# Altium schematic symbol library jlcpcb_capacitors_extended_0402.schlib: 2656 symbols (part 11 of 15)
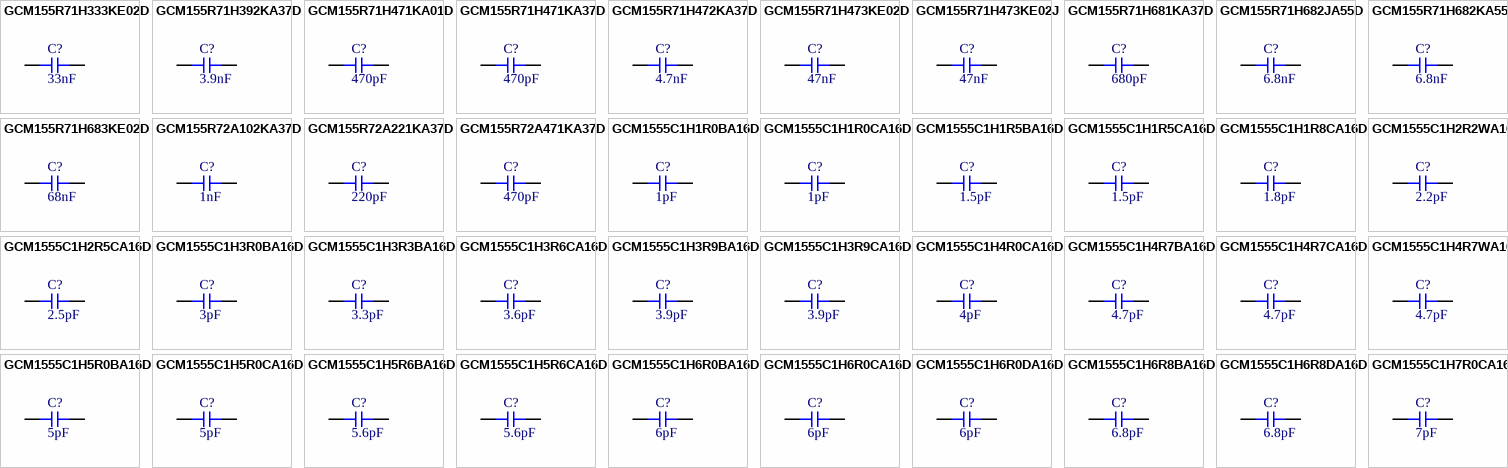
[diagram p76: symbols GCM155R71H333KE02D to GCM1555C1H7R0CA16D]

## GCM1555C1H4R7BA16D
designator C?  Capacitance: 4.7pF  (hidden comment: *)
Capacitor, Ceramic (MLCC), 4.7pF, ±0.1pF, 50V, C0G, ±0.1pF, SMD 0402; Manufacturer: Murata Electronics; Manufacturer Part Number: GCM1555C1H4R7BA16D
footprint CAP-0402 (0402 (1005M) Capacitor)
pins: 1, 2

## GCM1555C1H4R7CA16D
designator C?  Capacitance: 4.7pF  (hidden comment: *)
Capacitor, Ceramic (MLCC), 4.7pF, ±0.25pF, 50V, C0G, ±0.25pF, SMD 0402; Manufacturer: Murata Electronics; Manufacturer Part Number: GCM1555C1H4R7CA16D
footprint CAP-0402 (0402 (1005M) Capacitor)
pins: 1, 2

## GCM1555C1H4R7WA16D
designator C?  Capacitance: 4.7pF  (hidden comment: *)
Capacitor, Ceramic (MLCC), 4.7pF, ±0.05pF, 50V, C0G, ±0.05pF, SMD 0402; Manufacturer: Murata Electronics; Manufacturer Part Number: GCM1555C1H4R7WA16D
footprint CAP-0402 (0402 (1005M) Capacitor)
pins: 1, 2

## GCM1555C1H5R0BA16D
designator C?  Capacitance: 5pF  (hidden comment: *)
Capacitor, Ceramic (MLCC), 5pF, ±0.1pF, ±0.1pF, SMD 0402; Manufacturer: Murata Electronics; Manufacturer Part Number: GCM1555C1H5R0BA16D
footprint CAP-0402 (0402 (1005M) Capacitor)
pins: 1, 2

## GCM1555C1H5R0CA16D
designator C?  Capacitance: 5pF  (hidden comment: *)
Capacitor, Ceramic (MLCC), 5pF, ±0.25pF, 50V, C0G, ±0.25pF, SMD 0402; Manufacturer: Murata Electronics; Manufacturer Part Number: GCM1555C1H5R0CA16D
footprint CAP-0402 (0402 (1005M) Capacitor)
pins: 1, 2

## GCM1555C1H5R6BA16D
designator C?  Capacitance: 5.6pF  (hidden comment: *)
Capacitor, Ceramic (MLCC), 5.6pF, ±0.1pF, 50V, C0G, ±0.1pF, SMD 0402; Manufacturer: Murata Electronics; Manufacturer Part Number: GCM1555C1H5R6BA16D
footprint CAP-0402 (0402 (1005M) Capacitor)
pins: 1, 2

## GCM1555C1H5R6CA16D
designator C?  Capacitance: 5.6pF  (hidden comment: *)
Capacitor, Ceramic (MLCC), 5.6pF, ±0.25pF, 50V, C0G, ±0.25pF, SMD 0402; Manufacturer: Murata Electronics; Manufacturer Part Number: GCM1555C1H5R6CA16D
footprint CAP-0402 (0402 (1005M) Capacitor)
pins: 1, 2

## GCM1555C1H6R0BA16D
designator C?  Capacitance: 6pF  (hidden comment: *)
Capacitor, Ceramic (MLCC), 6pF, ±0.1pF, 50V, C0G, ±0.1pF, SMD 0402; Manufacturer: Murata Electronics; Manufacturer Part Number: GCM1555C1H6R0BA16D
footprint CAP-0402 (0402 (1005M) Capacitor)
pins: 1, 2

## GCM1555C1H6R0CA16D
designator C?  Capacitance: 6pF  (hidden comment: *)
Capacitor, Ceramic (MLCC), 6pF, ±0.25pF, 50V, C0G, ±0.25pF, SMD 0402; Manufacturer: Murata Electronics; Manufacturer Part Number: GCM1555C1H6R0CA16D
footprint CAP-0402 (0402 (1005M) Capacitor)
pins: 1, 2

## GCM1555C1H6R0DA16D
designator C?  Capacitance: 6pF  (hidden comment: *)
Capacitor, Ceramic (MLCC), 6pF, ±0.5pF, 50V, C0G, ±0.5pF, SMD 0402; Manufacturer: Murata Electronics; Manufacturer Part Number: GCM1555C1H6R0DA16D
footprint CAP-0402 (0402 (1005M) Capacitor)
pins: 1, 2

## GCM1555C1H6R8BA16D
designator C?  Capacitance: 6.8pF  (hidden comment: *)
Capacitor, Ceramic (MLCC), 6.8pF, ±0.1pF, 50V, C0G, ±0.1pF, SMD 0402; Manufacturer: Murata Electronics; Manufacturer Part Number: GCM1555C1H6R8BA16D
footprint CAP-0402 (0402 (1005M) Capacitor)
pins: 1, 2

## GCM1555C1H6R8DA16D
designator C?  Capacitance: 6.8pF  (hidden comment: *)
Capacitor, Ceramic (MLCC), 6.8pF, ±0.5pF, 50V, C0G, ±0.5pF, SMD 0402; Manufacturer: Murata Electronics; Manufacturer Part Number: GCM1555C1H6R8DA16D
footprint CAP-0402 (0402 (1005M) Capacitor)
pins: 1, 2

## GCM1555C1H7R0CA16D
designator C?  Capacitance: 7pF  (hidden comment: *)
Capacitor, Ceramic (MLCC), 7pF, ±0.25pF, 50V, C0G, ±0.25pF, SMD 0402; Manufacturer: Murata Electronics; Manufacturer Part Number: GCM1555C1H7R0CA16D
footprint CAP-0402 (0402 (1005M) Capacitor)
pins: 1, 2

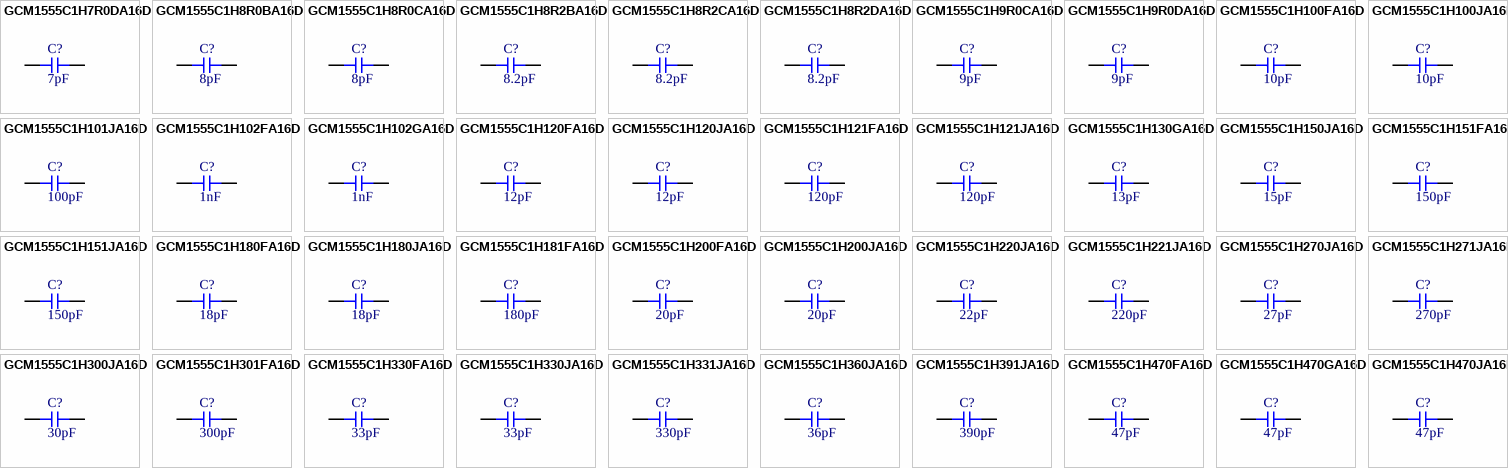
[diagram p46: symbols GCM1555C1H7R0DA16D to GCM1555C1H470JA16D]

## GCM1555C1H7R0DA16D
designator C?  Capacitance: 7pF  (hidden comment: *)
Capacitor, Ceramic (MLCC), 7pF, ±0.5pF, 50V, C0G, ±0.5pF, SMD 0402; Manufacturer: Murata Electronics; Manufacturer Part Number: GCM1555C1H7R0DA16D
footprint CAP-0402 (0402 (1005M) Capacitor)
pins: 1, 2

## GCM1555C1H8R0BA16D
designator C?  Capacitance: 8pF  (hidden comment: *)
Capacitor, Ceramic (MLCC), 8pF, ±0.1pF, 50V, C0G, ±0.1pF, SMD 0402; Manufacturer: Murata Electronics; Manufacturer Part Number: GCM1555C1H8R0BA16D
footprint CAP-0402 (0402 (1005M) Capacitor)
pins: 1, 2

## GCM1555C1H8R0CA16D
designator C?  Capacitance: 8pF  (hidden comment: *)
Capacitor, Ceramic (MLCC), 8pF, ±0.25pF, 50V, C0G, ±0.25pF, SMD 0402; Manufacturer: Murata Electronics; Manufacturer Part Number: GCM1555C1H8R0CA16D
footprint CAP-0402 (0402 (1005M) Capacitor)
pins: 1, 2

## GCM1555C1H8R2BA16D
designator C?  Capacitance: 8.2pF  (hidden comment: *)
Capacitor, Ceramic (MLCC), 8.2pF, ±0.1pF, 50V, C0G, ±0.1pF, SMD 0402; Manufacturer: Murata Electronics; Manufacturer Part Number: GCM1555C1H8R2BA16D
footprint CAP-0402 (0402 (1005M) Capacitor)
pins: 1, 2

## GCM1555C1H8R2CA16D
designator C?  Capacitance: 8.2pF  (hidden comment: *)
Capacitor, Ceramic (MLCC), 8.2pF, ±0.25pF, 50V, C0G, ±0.25pF, SMD 0402; Manufacturer: Murata Electronics; Manufacturer Part Number: GCM1555C1H8R2CA16D
footprint CAP-0402 (0402 (1005M) Capacitor)
pins: 1, 2

## GCM1555C1H8R2DA16D
designator C?  Capacitance: 8.2pF  (hidden comment: *)
Capacitor, Ceramic (MLCC), 8.2pF, ±0.5pF, 50V, C0G, ±0.5pF, SMD 0402; Manufacturer: Murata Electronics; Manufacturer Part Number: GCM1555C1H8R2DA16D
footprint CAP-0402 (0402 (1005M) Capacitor)
pins: 1, 2

## GCM1555C1H9R0CA16D
designator C?  Capacitance: 9pF  (hidden comment: *)
Capacitor, Ceramic (MLCC), 9pF, ±0.25pF, 50V, C0G, ±0.25pF, SMD 0402; Manufacturer: Murata Electronics; Manufacturer Part Number: GCM1555C1H9R0CA16D
footprint CAP-0402 (0402 (1005M) Capacitor)
pins: 1, 2

## GCM1555C1H9R0DA16D
designator C?  Capacitance: 9pF  (hidden comment: *)
Capacitor, Ceramic (MLCC), 9pF, ±0.5pF, 50V, C0G, ±0.5pF, SMD 0402; Manufacturer: Murata Electronics; Manufacturer Part Number: GCM1555C1H9R0DA16D
footprint CAP-0402 (0402 (1005M) Capacitor)
pins: 1, 2

## GCM1555C1H100FA16D
designator C?  Capacitance: 10pF  (hidden comment: *)
Capacitor, Ceramic (MLCC), 10pF, ±1%, 50V, C0G, ±1%, SMD 0402; Manufacturer: Murata Electronics; Manufacturer Part Number: GCM1555C1H100FA16D
footprint CAP-0402 (0402 (1005M) Capacitor)
pins: 1, 2

## GCM1555C1H100JA16D
designator C?  Capacitance: 10pF  (hidden comment: *)
Capacitor, Ceramic (MLCC), 10pF, ±5%, 50V, C0G, ±5%, SMD 0402; Manufacturer: Murata Electronics; Manufacturer Part Number: GCM1555C1H100JA16D
footprint CAP-0402 (0402 (1005M) Capacitor)
pins: 1, 2

## GCM1555C1H101JA16D
designator C?  Capacitance: 100pF  (hidden comment: *)
Capacitor, Ceramic (MLCC), 100pF, ±5%, 50V, C0G, ±5%, SMD 0402; Manufacturer: Murata Electronics; Manufacturer Part Number: GCM1555C1H101JA16D
footprint CAP-0402 (0402 (1005M) Capacitor)
pins: 1, 2

## GCM1555C1H102FA16D
designator C?  Capacitance: 1nF  (hidden comment: *)
Capacitor, Ceramic (MLCC), 1nF, ±1%, 50V, C0G, ±1%, SMD 0402; Manufacturer: Murata Electronics; Manufacturer Part Number: GCM1555C1H102FA16D
footprint CAP-0402 (0402 (1005M) Capacitor)
pins: 1, 2

## GCM1555C1H102GA16D
designator C?  Capacitance: 1nF  (hidden comment: *)
Capacitor, Ceramic (MLCC), 1nF, ±2%, 50V, C0G, ±2%, SMD 0402; Manufacturer: Murata Electronics; Manufacturer Part Number: GCM1555C1H102GA16D
footprint CAP-0402 (0402 (1005M) Capacitor)
pins: 1, 2

## GCM1555C1H120FA16D
designator C?  Capacitance: 12pF  (hidden comment: *)
Capacitor, Ceramic (MLCC), 12pF, ±1%, 50V, C0G, ±1%, SMD 0402; Manufacturer: Murata Electronics; Manufacturer Part Number: GCM1555C1H120FA16D
footprint CAP-0402 (0402 (1005M) Capacitor)
pins: 1, 2

## GCM1555C1H120JA16D
designator C?  Capacitance: 12pF  (hidden comment: *)
Capacitor, Ceramic (MLCC), 12pF, ±5%, 50V, C0G, ±5%, SMD 0402; Manufacturer: Murata Electronics; Manufacturer Part Number: GCM1555C1H120JA16D
footprint CAP-0402 (0402 (1005M) Capacitor)
pins: 1, 2

## GCM1555C1H121FA16D
designator C?  Capacitance: 120pF  (hidden comment: *)
Capacitor, Ceramic (MLCC), 120pF, ±1%, 50V, C0G, ±1%, SMD 0402; Manufacturer: Murata Electronics; Manufacturer Part Number: GCM1555C1H121FA16D
footprint CAP-0402 (0402 (1005M) Capacitor)
pins: 1, 2

## GCM1555C1H121JA16D
designator C?  Capacitance: 120pF  (hidden comment: *)
Capacitor, Ceramic (MLCC), 120pF, ±5%, 50V, C0G, ±5%, SMD 0402; Manufacturer: Murata Electronics; Manufacturer Part Number: GCM1555C1H121JA16D
footprint CAP-0402 (0402 (1005M) Capacitor)
pins: 1, 2

## GCM1555C1H130GA16D
designator C?  Capacitance: 13pF  (hidden comment: *)
Capacitor, Ceramic (MLCC), 13pF, ±2%, 50V, C0G, ±2%, SMD 0402; Manufacturer: Murata Electronics; Manufacturer Part Number: GCM1555C1H130GA16D
footprint CAP-0402 (0402 (1005M) Capacitor)
pins: 1, 2

## GCM1555C1H150JA16D
designator C?  Capacitance: 15pF  (hidden comment: *)
Capacitor, Ceramic (MLCC), 15pF, ±5%, 50V, C0G, ±5%, SMD 0402; Manufacturer: Murata Electronics; Manufacturer Part Number: GCM1555C1H150JA16D
footprint CAP-0402 (0402 (1005M) Capacitor)
pins: 1, 2

## GCM1555C1H151FA16D
designator C?  Capacitance: 150pF  (hidden comment: *)
Capacitor, Ceramic (MLCC), 150pF, ±1%, 50V, ±1%, SMD 0402; Manufacturer: Murata Electronics; Manufacturer Part Number: GCM1555C1H151FA16D
footprint CAP-0402 (0402 (1005M) Capacitor)
pins: 1, 2

## GCM1555C1H151JA16D
designator C?  Capacitance: 150pF  (hidden comment: *)
Capacitor, Ceramic (MLCC), 150pF, ±5%, 50V, C0G, ±5%, SMD 0402; Manufacturer: Murata Electronics; Manufacturer Part Number: GCM1555C1H151JA16D
footprint CAP-0402 (0402 (1005M) Capacitor)
pins: 1, 2

## GCM1555C1H180FA16D
designator C?  Capacitance: 18pF  (hidden comment: *)
Capacitor, Ceramic (MLCC), 18pF, ±1%, 50V, C0G, ±1%, SMD 0402; Manufacturer: Murata Electronics; Manufacturer Part Number: GCM1555C1H180FA16D
footprint CAP-0402 (0402 (1005M) Capacitor)
pins: 1, 2

## GCM1555C1H180JA16D
designator C?  Capacitance: 18pF  (hidden comment: *)
Capacitor, Ceramic (MLCC), 18pF, ±5%, 50V, C0G, ±5%, SMD 0402; Manufacturer: Murata Electronics; Manufacturer Part Number: GCM1555C1H180JA16D
footprint CAP-0402 (0402 (1005M) Capacitor)
pins: 1, 2

## GCM1555C1H181FA16D
designator C?  Capacitance: 180pF  (hidden comment: *)
Capacitor, Ceramic (MLCC), 180pF, ±1%, 50V, C0G, ±1%, SMD 0402; Manufacturer: Murata Electronics; Manufacturer Part Number: GCM1555C1H181FA16D
footprint CAP-0402 (0402 (1005M) Capacitor)
pins: 1, 2

## GCM1555C1H200FA16D
designator C?  Capacitance: 20pF  (hidden comment: *)
Capacitor, Ceramic (MLCC), 20pF, ±1%, 50V, C0G, ±1%, SMD 0402; Manufacturer: Murata Electronics; Manufacturer Part Number: GCM1555C1H200FA16D
footprint CAP-0402 (0402 (1005M) Capacitor)
pins: 1, 2

## GCM1555C1H200JA16D
designator C?  Capacitance: 20pF  (hidden comment: *)
Capacitor, Ceramic (MLCC), 20pF, ±5%, ±5%, SMD 0402; Manufacturer: Murata Electronics; Manufacturer Part Number: GCM1555C1H200JA16D
footprint CAP-0402 (0402 (1005M) Capacitor)
pins: 1, 2

## GCM1555C1H220JA16D
designator C?  Capacitance: 22pF  (hidden comment: *)
Capacitor, Ceramic (MLCC), 22pF, ±5%, 50V, C0G, ±5%, SMD 0402; Manufacturer: Murata Electronics; Manufacturer Part Number: GCM1555C1H220JA16D
footprint CAP-0402 (0402 (1005M) Capacitor)
pins: 1, 2

## GCM1555C1H221JA16D
designator C?  Capacitance: 220pF  (hidden comment: *)
Capacitor, Ceramic (MLCC), 220pF, ±5%, 50V, C0G, ±5%, SMD 0402; Manufacturer: Murata Electronics; Manufacturer Part Number: GCM1555C1H221JA16D
footprint CAP-0402 (0402 (1005M) Capacitor)
pins: 1, 2

## GCM1555C1H270JA16D
designator C?  Capacitance: 27pF  (hidden comment: *)
Capacitor, Ceramic (MLCC), 27pF, ±5%, 50V, C0G, ±5%, SMD 0402; Manufacturer: Murata Electronics; Manufacturer Part Number: GCM1555C1H270JA16D
footprint CAP-0402 (0402 (1005M) Capacitor)
pins: 1, 2

## GCM1555C1H271JA16D
designator C?  Capacitance: 270pF  (hidden comment: *)
Capacitor, Ceramic (MLCC), 270pF, ±5%, 50V, C0G, ±5%, SMD 0402; Manufacturer: Murata Electronics; Manufacturer Part Number: GCM1555C1H271JA16D
footprint CAP-0402 (0402 (1005M) Capacitor)
pins: 1, 2

## GCM1555C1H300JA16D
designator C?  Capacitance: 30pF  (hidden comment: *)
Capacitor, Ceramic (MLCC), 30pF, ±5%, 50V, C0G, ±5%, SMD 0402; Manufacturer: Murata Electronics; Manufacturer Part Number: GCM1555C1H300JA16D
footprint CAP-0402 (0402 (1005M) Capacitor)
pins: 1, 2

## GCM1555C1H301FA16D
designator C?  Capacitance: 300pF  (hidden comment: *)
Capacitor, Ceramic (MLCC), 300pF, ±1%, 50V, C0G, ±1%, SMD 0402; Manufacturer: Murata Electronics; Manufacturer Part Number: GCM1555C1H301FA16D
footprint CAP-0402 (0402 (1005M) Capacitor)
pins: 1, 2

## GCM1555C1H330FA16D
designator C?  Capacitance: 33pF  (hidden comment: *)
Capacitor, Ceramic (MLCC), 33pF, ±1%, 50V, C0G, ±1%, SMD 0402; Manufacturer: Murata Electronics; Manufacturer Part Number: GCM1555C1H330FA16D
footprint CAP-0402 (0402 (1005M) Capacitor)
pins: 1, 2

## GCM1555C1H330JA16D
designator C?  Capacitance: 33pF  (hidden comment: *)
Capacitor, Ceramic (MLCC), 33pF, ±5%, 50V, C0G, ±5%, SMD 0402; Manufacturer: Murata Electronics; Manufacturer Part Number: GCM1555C1H330JA16D
footprint CAP-0402 (0402 (1005M) Capacitor)
pins: 1, 2

## GCM1555C1H331JA16D
designator C?  Capacitance: 330pF  (hidden comment: *)
Capacitor, Ceramic (MLCC), 330pF, ±5%, 50V, C0G, ±5%, SMD 0402; Manufacturer: Murata Electronics; Manufacturer Part Number: GCM1555C1H331JA16D
footprint CAP-0402 (0402 (1005M) Capacitor)
pins: 1, 2

## GCM1555C1H360JA16D
designator C?  Capacitance: 36pF  (hidden comment: *)
Capacitor, Ceramic (MLCC), 36pF, ±5%, 50V, C0G, ±5%, SMD 0402; Manufacturer: Murata Electronics; Manufacturer Part Number: GCM1555C1H360JA16D
footprint CAP-0402 (0402 (1005M) Capacitor)
pins: 1, 2

## GCM1555C1H391JA16D
designator C?  Capacitance: 390pF  (hidden comment: *)
Capacitor, Ceramic (MLCC), 390pF, ±5%, 50V, C0G, ±5%, SMD 0402; Manufacturer: Murata Electronics; Manufacturer Part Number: GCM1555C1H391JA16D
footprint CAP-0402 (0402 (1005M) Capacitor)
pins: 1, 2

## GCM1555C1H470FA16D
designator C?  Capacitance: 47pF  (hidden comment: *)
Capacitor, Ceramic (MLCC), 47pF, ±1%, 50V, C0G, ±1%, SMD 0402; Manufacturer: Murata Electronics; Manufacturer Part Number: GCM1555C1H470FA16D
footprint CAP-0402 (0402 (1005M) Capacitor)
pins: 1, 2

## GCM1555C1H470GA16D
designator C?  Capacitance: 47pF  (hidden comment: *)
Capacitor, Ceramic (MLCC), 47pF, ±2%, 50V, C0G, ±2%, SMD 0402; Manufacturer: Murata Electronics; Manufacturer Part Number: GCM1555C1H470GA16D
footprint CAP-0402 (0402 (1005M) Capacitor)
pins: 1, 2

## GCM1555C1H470JA16D
designator C?  Capacitance: 47pF  (hidden comment: *)
Capacitor, Ceramic (MLCC), 47pF, ±5%, 50V, C0G, ±5%, SMD 0402; Manufacturer: Murata Electronics; Manufacturer Part Number: GCM1555C1H470JA16D
footprint CAP-0402 (0402 (1005M) Capacitor)
pins: 1, 2

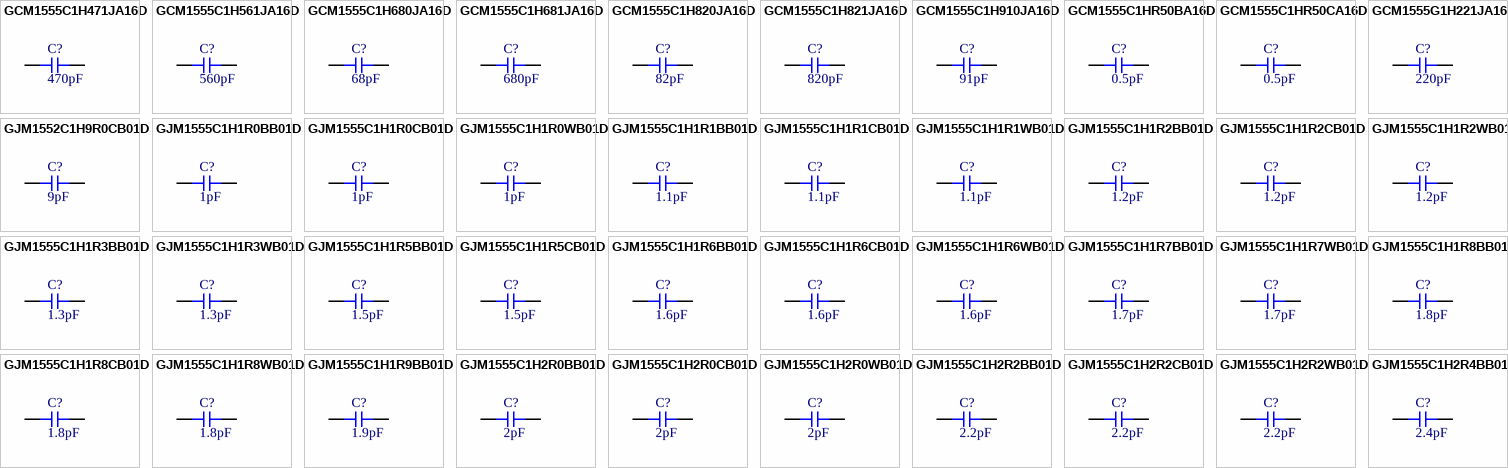
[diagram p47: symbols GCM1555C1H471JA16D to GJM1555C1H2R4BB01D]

## GCM1555C1H471JA16D
designator C?  Capacitance: 470pF  (hidden comment: *)
Capacitor, Ceramic (MLCC), 470pF, ±5%, 50V, C0G, ±5%, SMD 0402; Manufacturer: Murata Electronics; Manufacturer Part Number: GCM1555C1H471JA16D
footprint CAP-0402 (0402 (1005M) Capacitor)
pins: 1, 2

## GCM1555C1H561JA16D
designator C?  Capacitance: 560pF  (hidden comment: *)
Capacitor, Ceramic (MLCC), 560pF, ±5%, 50V, C0G, ±5%, SMD 0402; Manufacturer: Murata Electronics; Manufacturer Part Number: GCM1555C1H561JA16D
footprint CAP-0402 (0402 (1005M) Capacitor)
pins: 1, 2

## GCM1555C1H680JA16D
designator C?  Capacitance: 68pF  (hidden comment: *)
Capacitor, Ceramic (MLCC), 68pF, ±5%, 50V, C0G, ±5%, SMD 0402; Manufacturer: Murata Electronics; Manufacturer Part Number: GCM1555C1H680JA16D
footprint CAP-0402 (0402 (1005M) Capacitor)
pins: 1, 2

## GCM1555C1H681JA16D
designator C?  Capacitance: 680pF  (hidden comment: *)
Capacitor, Ceramic (MLCC), 680pF, ±5%, 50V, C0G, ±5%, SMD 0402; Manufacturer: Murata Electronics; Manufacturer Part Number: GCM1555C1H681JA16D
footprint CAP-0402 (0402 (1005M) Capacitor)
pins: 1, 2

## GCM1555C1H820JA16D
designator C?  Capacitance: 82pF  (hidden comment: *)
Capacitor, Ceramic (MLCC), 82pF, ±5%, 50V, C0G, ±5%, SMD 0402; Manufacturer: Murata Electronics; Manufacturer Part Number: GCM1555C1H820JA16D
footprint CAP-0402 (0402 (1005M) Capacitor)
pins: 1, 2

## GCM1555C1H821JA16D
designator C?  Capacitance: 820pF  (hidden comment: *)
Capacitor, Ceramic (MLCC), 820pF, ±5%, 50V, C0G, ±5%, SMD 0402; Manufacturer: Murata Electronics; Manufacturer Part Number: GCM1555C1H821JA16D
footprint CAP-0402 (0402 (1005M) Capacitor)
pins: 1, 2

## GCM1555C1H910JA16D
designator C?  Capacitance: 91pF  (hidden comment: *)
Capacitor, Ceramic (MLCC), 91pF, ±5%, 50V, ±5%, SMD 0402; Manufacturer: Murata Electronics; Manufacturer Part Number: GCM1555C1H910JA16D
footprint CAP-0402 (0402 (1005M) Capacitor)
pins: 1, 2

## GCM1555C1HR50BA16D
designator C?  Capacitance: 0.5pF  (hidden comment: *)
Capacitor, Ceramic (MLCC), 0.5pF, ±0.1pF, 50V, C0G, ±0.1pF, SMD 0402; Manufacturer: Murata Electronics; Manufacturer Part Number: GCM1555C1HR50BA16D
footprint CAP-0402 (0402 (1005M) Capacitor)
pins: 1, 2

## GCM1555C1HR50CA16D
designator C?  Capacitance: 0.5pF  (hidden comment: *)
Capacitor, Ceramic (MLCC), 0.5pF, ±0.25pF, 50V, C0G, ±0.25pF, SMD 0402; Manufacturer: Murata Electronics; Manufacturer Part Number: GCM1555C1HR50CA16D
footprint CAP-0402 (0402 (1005M) Capacitor)
pins: 1, 2

## GCM1555G1H221JA16D
designator C?  Capacitance: 220pF  (hidden comment: *)
Capacitor, Ceramic (MLCC), 220pF, ±5%, 50V, X6S, ±5%, SMD 0402; Manufacturer: Murata Electronics; Manufacturer Part Number: GCM1555G1H221JA16D
footprint CAP-0402 (0402 (1005M) Capacitor)
pins: 1, 2

## GJM1552C1H9R0CB01D
designator C?  Capacitance: 9pF  (hidden comment: *)
Capacitor, Ceramic (MLCC), 9pF, ±0.25pF, 50V, CH, ±0.25pF, SMD 0402; Manufacturer: Murata Electronics; Manufacturer Part Number: GJM1552C1H9R0CB01D
footprint CAP-0402 (0402 (1005M) Capacitor)
pins: 1, 2

## GJM1555C1H1R0BB01D
designator C?  Capacitance: 1pF  (hidden comment: *)
Capacitor, Ceramic (MLCC), 1pF, ±0.1pF, 50V, C0G, ±0.1pF, SMD 0402; Manufacturer: Murata Electronics; Manufacturer Part Number: GJM1555C1H1R0BB01D
footprint CAP-0402 (0402 (1005M) Capacitor)
pins: 1, 2

## GJM1555C1H1R0CB01D
designator C?  Capacitance: 1pF  (hidden comment: *)
Capacitor, Ceramic (MLCC), 1pF, ±0.25pF, 50V, C0G, ±0.25pF, SMD 0402; Manufacturer: Murata Electronics; Manufacturer Part Number: GJM1555C1H1R0CB01D
footprint CAP-0402 (0402 (1005M) Capacitor)
pins: 1, 2

## GJM1555C1H1R0WB01D
designator C?  Capacitance: 1pF  (hidden comment: *)
Capacitor, Ceramic (MLCC), 1pF, ±0.05pF, 50V, C0G, ±0.05pF, SMD 0402; Manufacturer: Murata Electronics; Manufacturer Part Number: GJM1555C1H1R0WB01D
footprint CAP-0402 (0402 (1005M) Capacitor)
pins: 1, 2

## GJM1555C1H1R1BB01D
designator C?  Capacitance: 1.1pF  (hidden comment: *)
Capacitor, Ceramic (MLCC), 1.1pF, ±0.1pF, 50V, C0G, ±0.1pF, SMD 0402; Manufacturer: Murata Electronics; Manufacturer Part Number: GJM1555C1H1R1BB01D
footprint CAP-0402 (0402 (1005M) Capacitor)
pins: 1, 2

## GJM1555C1H1R1CB01D
designator C?  Capacitance: 1.1pF  (hidden comment: *)
Capacitor, Ceramic (MLCC), 1.1pF, ±0.25pF, 50V, C0G, ±0.25pF, SMD 0402; Manufacturer: Murata Electronics; Manufacturer Part Number: GJM1555C1H1R1CB01D
footprint CAP-0402 (0402 (1005M) Capacitor)
pins: 1, 2

## GJM1555C1H1R1WB01D
designator C?  Capacitance: 1.1pF  (hidden comment: *)
Capacitor, Ceramic (MLCC), 1.1pF, ±0.05pF, 50V, C0G, ±0.05pF, SMD 0402; Manufacturer: Murata Electronics; Manufacturer Part Number: GJM1555C1H1R1WB01D
footprint CAP-0402 (0402 (1005M) Capacitor)
pins: 1, 2

## GJM1555C1H1R2BB01D
designator C?  Capacitance: 1.2pF  (hidden comment: *)
Capacitor, Ceramic (MLCC), 1.2pF, ±0.1pF, 50V, C0G, ±0.1pF, SMD 0402; Manufacturer: Murata Electronics; Manufacturer Part Number: GJM1555C1H1R2BB01D
footprint CAP-0402 (0402 (1005M) Capacitor)
pins: 1, 2

## GJM1555C1H1R2CB01D
designator C?  Capacitance: 1.2pF  (hidden comment: *)
Capacitor, Ceramic (MLCC), 1.2pF, ±0.25pF, 50V, C0G, ±0.25pF, SMD 0402; Manufacturer: Murata Electronics; Manufacturer Part Number: GJM1555C1H1R2CB01D
footprint CAP-0402 (0402 (1005M) Capacitor)
pins: 1, 2

## GJM1555C1H1R2WB01D
designator C?  Capacitance: 1.2pF  (hidden comment: *)
Capacitor, Ceramic (MLCC), 1.2pF, ±0.05pF, 50V, C0G, ±0.05pF, SMD 0402; Manufacturer: Murata Electronics; Manufacturer Part Number: GJM1555C1H1R2WB01D
footprint CAP-0402 (0402 (1005M) Capacitor)
pins: 1, 2

## GJM1555C1H1R3BB01D
designator C?  Capacitance: 1.3pF  (hidden comment: *)
Capacitor, Ceramic (MLCC), 1.3pF, ±0.1pF, 50V, C0G, ±0.1pF, SMD 0402; Manufacturer: Murata Electronics; Manufacturer Part Number: GJM1555C1H1R3BB01D
footprint CAP-0402 (0402 (1005M) Capacitor)
pins: 1, 2

## GJM1555C1H1R3WB01D
designator C?  Capacitance: 1.3pF  (hidden comment: *)
Capacitor, Ceramic (MLCC), 1.3pF, ±0.05pF, 50V, C0G, ±0.05pF, SMD 0402; Manufacturer: Murata Electronics; Manufacturer Part Number: GJM1555C1H1R3WB01D
footprint CAP-0402 (0402 (1005M) Capacitor)
pins: 1, 2

## GJM1555C1H1R5BB01D
designator C?  Capacitance: 1.5pF  (hidden comment: *)
Capacitor, Ceramic (MLCC), 1.5pF, ±0.1pF, 50V, C0G, ±0.1pF, SMD 0402; Manufacturer: Murata Electronics; Manufacturer Part Number: GJM1555C1H1R5BB01D
footprint CAP-0402 (0402 (1005M) Capacitor)
pins: 1, 2

## GJM1555C1H1R5CB01D
designator C?  Capacitance: 1.5pF  (hidden comment: *)
Capacitor, Ceramic (MLCC), 1.5pF, ±0.25pF, 50V, C0G, ±0.25pF, SMD 0402; Manufacturer: Murata Electronics; Manufacturer Part Number: GJM1555C1H1R5CB01D
footprint CAP-0402 (0402 (1005M) Capacitor)
pins: 1, 2

## GJM1555C1H1R6BB01D
designator C?  Capacitance: 1.6pF  (hidden comment: *)
Capacitor, Ceramic (MLCC), 1.6pF, ±0.1pF, 50V, C0G, ±0.1pF, SMD 0402; Manufacturer: Murata Electronics; Manufacturer Part Number: GJM1555C1H1R6BB01D
footprint CAP-0402 (0402 (1005M) Capacitor)
pins: 1, 2

## GJM1555C1H1R6CB01D
designator C?  Capacitance: 1.6pF  (hidden comment: *)
Capacitor, Ceramic (MLCC), 1.6pF, ±0.25pF, 50V, C0G, ±0.25pF, SMD 0402; Manufacturer: Murata Electronics; Manufacturer Part Number: GJM1555C1H1R6CB01D
footprint CAP-0402 (0402 (1005M) Capacitor)
pins: 1, 2

## GJM1555C1H1R6WB01D
designator C?  Capacitance: 1.6pF  (hidden comment: *)
Capacitor, Ceramic (MLCC), 1.6pF, ±0.05pF, 50V, C0G, ±0.05pF, SMD 0402; Manufacturer: Murata Electronics; Manufacturer Part Number: GJM1555C1H1R6WB01D
footprint CAP-0402 (0402 (1005M) Capacitor)
pins: 1, 2

## GJM1555C1H1R7BB01D
designator C?  Capacitance: 1.7pF  (hidden comment: *)
Capacitor, Ceramic (MLCC), 1.7pF, ±0.1pF, 50V, C0G, ±0.1pF, SMD 0402; Manufacturer: Murata Electronics; Manufacturer Part Number: GJM1555C1H1R7BB01D
footprint CAP-0402 (0402 (1005M) Capacitor)
pins: 1, 2

## GJM1555C1H1R7WB01D
designator C?  Capacitance: 1.7pF  (hidden comment: *)
Capacitor, Ceramic (MLCC), 1.7pF, ±0.05pF, 50V, C0G, ±0.05pF, SMD 0402; Manufacturer: Murata Electronics; Manufacturer Part Number: GJM1555C1H1R7WB01D
footprint CAP-0402 (0402 (1005M) Capacitor)
pins: 1, 2

## GJM1555C1H1R8BB01D
designator C?  Capacitance: 1.8pF  (hidden comment: *)
Capacitor, Ceramic (MLCC), 1.8pF, ±0.1pF, 50V, C0G, ±0.1pF, SMD 0402; Manufacturer: Murata Electronics; Manufacturer Part Number: GJM1555C1H1R8BB01D
footprint CAP-0402 (0402 (1005M) Capacitor)
pins: 1, 2

## GJM1555C1H1R8CB01D
designator C?  Capacitance: 1.8pF  (hidden comment: *)
Capacitor, Ceramic (MLCC), 1.8pF, ±0.25pF, 50V, C0G, ±0.25pF, SMD 0402; Manufacturer: Murata Electronics; Manufacturer Part Number: GJM1555C1H1R8CB01D
footprint CAP-0402 (0402 (1005M) Capacitor)
pins: 1, 2

## GJM1555C1H1R8WB01D
designator C?  Capacitance: 1.8pF  (hidden comment: *)
Capacitor, Ceramic (MLCC), 1.8pF, ±0.05pF, 50V, C0G, ±0.05pF, SMD 0402; Manufacturer: Murata Electronics; Manufacturer Part Number: GJM1555C1H1R8WB01D
footprint CAP-0402 (0402 (1005M) Capacitor)
pins: 1, 2

## GJM1555C1H1R9BB01D
designator C?  Capacitance: 1.9pF  (hidden comment: *)
Capacitor, Ceramic (MLCC), 1.9pF, ±0.1pF, 50V, C0G, ±0.1pF, SMD 0402; Manufacturer: Murata Electronics; Manufacturer Part Number: GJM1555C1H1R9BB01D
footprint CAP-0402 (0402 (1005M) Capacitor)
pins: 1, 2

## GJM1555C1H2R0BB01D
designator C?  Capacitance: 2pF  (hidden comment: *)
Capacitor, Ceramic (MLCC), 2pF, ±0.1pF, 50V, C0G, ±0.1pF, SMD 0402; Manufacturer: Murata Electronics; Manufacturer Part Number: GJM1555C1H2R0BB01D
footprint CAP-0402 (0402 (1005M) Capacitor)
pins: 1, 2

## GJM1555C1H2R0CB01D
designator C?  Capacitance: 2pF  (hidden comment: *)
Capacitor, Ceramic (MLCC), 2pF, ±0.25pF, 50V, C0G, ±0.25pF, SMD 0402; Manufacturer: Murata Electronics; Manufacturer Part Number: GJM1555C1H2R0CB01D
footprint CAP-0402 (0402 (1005M) Capacitor)
pins: 1, 2

## GJM1555C1H2R0WB01D
designator C?  Capacitance: 2pF  (hidden comment: *)
Capacitor, Ceramic (MLCC), 2pF, ±0.05pF, 50V, C0G, ±0.05pF, SMD 0402; Manufacturer: Murata Electronics; Manufacturer Part Number: GJM1555C1H2R0WB01D
footprint CAP-0402 (0402 (1005M) Capacitor)
pins: 1, 2

## GJM1555C1H2R2BB01D
designator C?  Capacitance: 2.2pF  (hidden comment: *)
Capacitor, Ceramic (MLCC), 2.2pF, ±0.1pF, 50V, C0G, ±0.1pF, SMD 0402; Manufacturer: Murata Electronics; Manufacturer Part Number: GJM1555C1H2R2BB01D
footprint CAP-0402 (0402 (1005M) Capacitor)
pins: 1, 2

## GJM1555C1H2R2CB01D
designator C?  Capacitance: 2.2pF  (hidden comment: *)
Capacitor, Ceramic (MLCC), 2.2pF, ±0.25pF, 50V, C0G, ±0.25pF, SMD 0402; Manufacturer: Murata Electronics; Manufacturer Part Number: GJM1555C1H2R2CB01D
footprint CAP-0402 (0402 (1005M) Capacitor)
pins: 1, 2

## GJM1555C1H2R2WB01D
designator C?  Capacitance: 2.2pF  (hidden comment: *)
Capacitor, Ceramic (MLCC), 2.2pF, ±0.05pF, 50V, C0G, ±0.05pF, SMD 0402; Manufacturer: Murata Electronics; Manufacturer Part Number: GJM1555C1H2R2WB01D
footprint CAP-0402 (0402 (1005M) Capacitor)
pins: 1, 2

## GJM1555C1H2R4BB01D
designator C?  Capacitance: 2.4pF  (hidden comment: *)
Capacitor, Ceramic (MLCC), 2.4pF, ±0.1pF, 50V, C0G, ±0.1pF, SMD 0402; Manufacturer: Murata Electronics; Manufacturer Part Number: GJM1555C1H2R4BB01D
footprint CAP-0402 (0402 (1005M) Capacitor)
pins: 1, 2

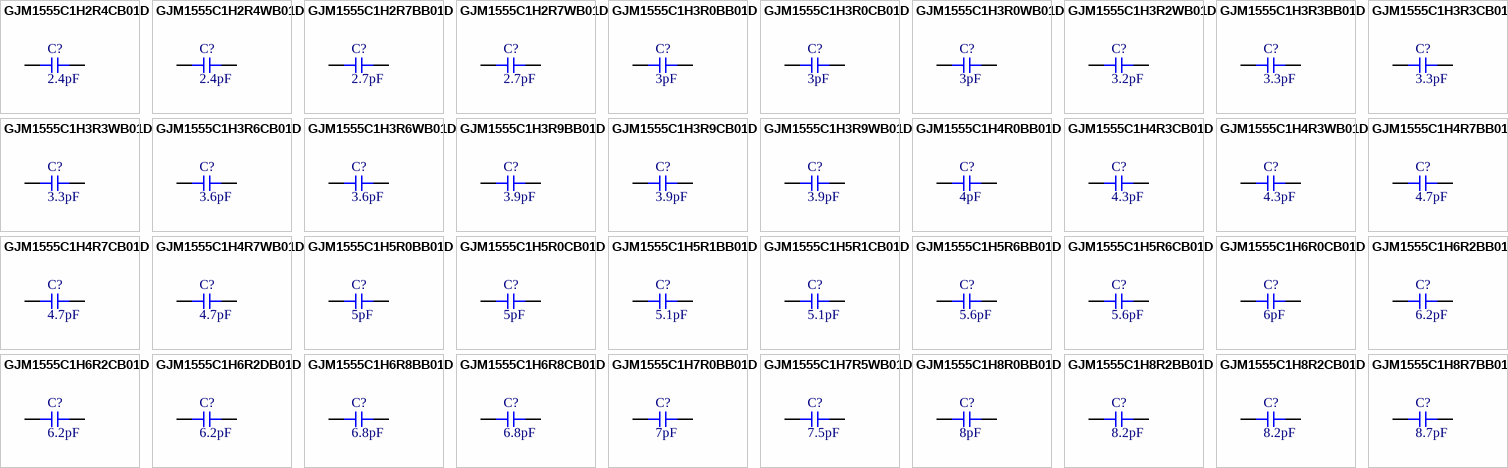
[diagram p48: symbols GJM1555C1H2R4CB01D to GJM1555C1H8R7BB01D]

## GJM1555C1H2R4CB01D
designator C?  Capacitance: 2.4pF  (hidden comment: *)
Capacitor, Ceramic (MLCC), 2.4pF, ±0.25pF, 50V, C0G, ±0.25pF, SMD 0402; Manufacturer: Murata Electronics; Manufacturer Part Number: GJM1555C1H2R4CB01D
footprint CAP-0402 (0402 (1005M) Capacitor)
pins: 1, 2

## GJM1555C1H2R4WB01D
designator C?  Capacitance: 2.4pF  (hidden comment: *)
Capacitor, Ceramic (MLCC), 2.4pF, ±0.05pF, 50V, C0G, ±0.05pF, SMD 0402; Manufacturer: Murata Electronics; Manufacturer Part Number: GJM1555C1H2R4WB01D
footprint CAP-0402 (0402 (1005M) Capacitor)
pins: 1, 2

## GJM1555C1H2R7BB01D
designator C?  Capacitance: 2.7pF  (hidden comment: *)
Capacitor, Ceramic (MLCC), 2.7pF, ±0.1pF, 50V, C0G, ±0.1pF, SMD 0402; Manufacturer: Murata Electronics; Manufacturer Part Number: GJM1555C1H2R7BB01D
footprint CAP-0402 (0402 (1005M) Capacitor)
pins: 1, 2

## GJM1555C1H2R7WB01D
designator C?  Capacitance: 2.7pF  (hidden comment: *)
Capacitor, Ceramic (MLCC), 2.7pF, ±0.05pF, 50V, C0G, ±0.05pF, SMD 0402; Manufacturer: Murata Electronics; Manufacturer Part Number: GJM1555C1H2R7WB01D
footprint CAP-0402 (0402 (1005M) Capacitor)
pins: 1, 2

## GJM1555C1H3R0BB01D
designator C?  Capacitance: 3pF  (hidden comment: *)
Capacitor, Ceramic (MLCC), 3pF, ±0.1pF, 50V, C0G, ±0.1pF, SMD 0402; Manufacturer: Murata Electronics; Manufacturer Part Number: GJM1555C1H3R0BB01D
footprint CAP-0402 (0402 (1005M) Capacitor)
pins: 1, 2

## GJM1555C1H3R0CB01D
designator C?  Capacitance: 3pF  (hidden comment: *)
Capacitor, Ceramic (MLCC), 3pF, ±0.25pF, ±0.25pF, SMD 0402; Manufacturer: Murata Electronics; Manufacturer Part Number: GJM1555C1H3R0CB01D
footprint CAP-0402 (0402 (1005M) Capacitor)
pins: 1, 2

## GJM1555C1H3R0WB01D
designator C?  Capacitance: 3pF  (hidden comment: *)
Capacitor, Ceramic (MLCC), 3pF, ±0.05pF, 50V, C0G, ±0.05pF, SMD 0402; Manufacturer: Murata Electronics; Manufacturer Part Number: GJM1555C1H3R0WB01D
footprint CAP-0402 (0402 (1005M) Capacitor)
pins: 1, 2

## GJM1555C1H3R2WB01D
designator C?  Capacitance: 3.2pF  (hidden comment: *)
Capacitor, Ceramic (MLCC), 3.2pF, ±0.05pF, 50V, C0G, ±0.05pF, SMD 0402; Manufacturer: Murata Electronics; Manufacturer Part Number: GJM1555C1H3R2WB01D
footprint CAP-0402 (0402 (1005M) Capacitor)
pins: 1, 2

## GJM1555C1H3R3BB01D
designator C?  Capacitance: 3.3pF  (hidden comment: *)
Capacitor, Ceramic (MLCC), 3.3pF, ±0.1pF, 50V, C0G, ±0.1pF, SMD 0402; Manufacturer: Murata Electronics; Manufacturer Part Number: GJM1555C1H3R3BB01D
footprint CAP-0402 (0402 (1005M) Capacitor)
pins: 1, 2

## GJM1555C1H3R3CB01D
designator C?  Capacitance: 3.3pF  (hidden comment: *)
Capacitor, Ceramic (MLCC), 3.3pF, ±0.25pF, 50V, C0G, ±0.25pF, SMD 0402; Manufacturer: Murata Electronics; Manufacturer Part Number: GJM1555C1H3R3CB01D
footprint CAP-0402 (0402 (1005M) Capacitor)
pins: 1, 2

## GJM1555C1H3R3WB01D
designator C?  Capacitance: 3.3pF  (hidden comment: *)
Capacitor, Ceramic (MLCC), 3.3pF, ±0.05pF, 50V, C0G, ±0.05pF, SMD 0402; Manufacturer: Murata Electronics; Manufacturer Part Number: GJM1555C1H3R3WB01D
footprint CAP-0402 (0402 (1005M) Capacitor)
pins: 1, 2

## GJM1555C1H3R6CB01D
designator C?  Capacitance: 3.6pF  (hidden comment: *)
Capacitor, Ceramic (MLCC), 3.6pF, ±0.25pF, 50V, C0G, ±0.25pF, SMD 0402; Manufacturer: Murata Electronics; Manufacturer Part Number: GJM1555C1H3R6CB01D
footprint CAP-0402 (0402 (1005M) Capacitor)
pins: 1, 2

## GJM1555C1H3R6WB01D
designator C?  Capacitance: 3.6pF  (hidden comment: *)
Capacitor, Ceramic (MLCC), 3.6pF, ±0.05pF, 50V, C0G, ±0.05pF, SMD 0402; Manufacturer: Murata Electronics; Manufacturer Part Number: GJM1555C1H3R6WB01D
footprint CAP-0402 (0402 (1005M) Capacitor)
pins: 1, 2

## GJM1555C1H3R9BB01D
designator C?  Capacitance: 3.9pF  (hidden comment: *)
Capacitor, Ceramic (MLCC), 3.9pF, ±0.1pF, 50V, C0G, ±0.1pF, SMD 0402; Manufacturer: Murata Electronics; Manufacturer Part Number: GJM1555C1H3R9BB01D
footprint CAP-0402 (0402 (1005M) Capacitor)
pins: 1, 2

## GJM1555C1H3R9CB01D
designator C?  Capacitance: 3.9pF  (hidden comment: *)
Capacitor, Ceramic (MLCC), 3.9pF, ±0.25pF, 50V, C0G, ±0.25pF, SMD 0402; Manufacturer: Murata Electronics; Manufacturer Part Number: GJM1555C1H3R9CB01D
footprint CAP-0402 (0402 (1005M) Capacitor)
pins: 1, 2

## GJM1555C1H3R9WB01D
designator C?  Capacitance: 3.9pF  (hidden comment: *)
Capacitor, Ceramic (MLCC), 3.9pF, ±0.05pF, 50V, C0G, ±0.05pF, SMD 0402; Manufacturer: Murata Electronics; Manufacturer Part Number: GJM1555C1H3R9WB01D
footprint CAP-0402 (0402 (1005M) Capacitor)
pins: 1, 2

## GJM1555C1H4R0BB01D
designator C?  Capacitance: 4pF  (hidden comment: *)
Capacitor, Ceramic (MLCC), 4pF, ±0.1pF, 50V, C0G, ±0.1pF, SMD 0402; Manufacturer: Murata Electronics; Manufacturer Part Number: GJM1555C1H4R0BB01D
footprint CAP-0402 (0402 (1005M) Capacitor)
pins: 1, 2

## GJM1555C1H4R3CB01D
designator C?  Capacitance: 4.3pF  (hidden comment: *)
Capacitor, Ceramic (MLCC), 4.3pF, ±0.25pF, 50V, C0G, ±0.25pF, SMD 0402; Manufacturer: Murata Electronics; Manufacturer Part Number: GJM1555C1H4R3CB01D
footprint CAP-0402 (0402 (1005M) Capacitor)
pins: 1, 2

## GJM1555C1H4R3WB01D
designator C?  Capacitance: 4.3pF  (hidden comment: *)
Capacitor, Ceramic (MLCC), 4.3pF, ±0.05pF, 50V, C0G, ±0.05pF, SMD 0402; Manufacturer: Murata Electronics; Manufacturer Part Number: GJM1555C1H4R3WB01D
footprint CAP-0402 (0402 (1005M) Capacitor)
pins: 1, 2

## GJM1555C1H4R7BB01D
designator C?  Capacitance: 4.7pF  (hidden comment: *)
Capacitor, Ceramic (MLCC), 4.7pF, ±0.1pF, 50V, C0G, ±0.1pF, SMD 0402; Manufacturer: Murata Electronics; Manufacturer Part Number: GJM1555C1H4R7BB01D
footprint CAP-0402 (0402 (1005M) Capacitor)
pins: 1, 2

## GJM1555C1H4R7CB01D
designator C?  Capacitance: 4.7pF  (hidden comment: *)
Capacitor, Ceramic (MLCC), 4.7pF, ±0.25pF, 50V, C0G, ±0.25pF, SMD 0402; Manufacturer: Murata Electronics; Manufacturer Part Number: GJM1555C1H4R7CB01D
footprint CAP-0402 (0402 (1005M) Capacitor)
pins: 1, 2

## GJM1555C1H4R7WB01D
designator C?  Capacitance: 4.7pF  (hidden comment: *)
Capacitor, Ceramic (MLCC), 4.7pF, ±0.05pF, 50V, C0G, ±0.05pF, SMD 0402; Manufacturer: Murata Electronics; Manufacturer Part Number: GJM1555C1H4R7WB01D
footprint CAP-0402 (0402 (1005M) Capacitor)
pins: 1, 2

## GJM1555C1H5R0BB01D
designator C?  Capacitance: 5pF  (hidden comment: *)
Capacitor, Ceramic (MLCC), 5pF, ±0.1pF, 50V, C0G, ±0.1pF, SMD 0402; Manufacturer: Murata Electronics; Manufacturer Part Number: GJM1555C1H5R0BB01D
footprint CAP-0402 (0402 (1005M) Capacitor)
pins: 1, 2

## GJM1555C1H5R0CB01D
designator C?  Capacitance: 5pF  (hidden comment: *)
Capacitor, Ceramic (MLCC), 5pF, ±0.25pF, 50V, C0G, ±0.25pF, SMD 0402; Manufacturer: Murata Electronics; Manufacturer Part Number: GJM1555C1H5R0CB01D
footprint CAP-0402 (0402 (1005M) Capacitor)
pins: 1, 2

## GJM1555C1H5R1BB01D
designator C?  Capacitance: 5.1pF  (hidden comment: *)
Capacitor, Ceramic (MLCC), 5.1pF, ±0.1pF, 50V, C0G, ±0.1pF, SMD 0402; Manufacturer: Murata Electronics; Manufacturer Part Number: GJM1555C1H5R1BB01D
footprint CAP-0402 (0402 (1005M) Capacitor)
pins: 1, 2

## GJM1555C1H5R1CB01D
designator C?  Capacitance: 5.1pF  (hidden comment: *)
Capacitor, Ceramic (MLCC), 5.1pF, ±0.25pF, ±0.25pF, SMD 0402; Manufacturer: Murata Electronics; Manufacturer Part Number: GJM1555C1H5R1CB01D
footprint CAP-0402 (0402 (1005M) Capacitor)
pins: 1, 2

## GJM1555C1H5R6BB01D
designator C?  Capacitance: 5.6pF  (hidden comment: *)
Capacitor, Ceramic (MLCC), 5.6pF, ±0.1pF, 50V, C0G, ±0.1pF, SMD 0402; Manufacturer: Murata Electronics; Manufacturer Part Number: GJM1555C1H5R6BB01D
footprint CAP-0402 (0402 (1005M) Capacitor)
pins: 1, 2

## GJM1555C1H5R6CB01D
designator C?  Capacitance: 5.6pF  (hidden comment: *)
Capacitor, Ceramic (MLCC), 5.6pF, ±0.25pF, 50V, C0G, ±0.25pF, SMD 0402; Manufacturer: Murata Electronics; Manufacturer Part Number: GJM1555C1H5R6CB01D
footprint CAP-0402 (0402 (1005M) Capacitor)
pins: 1, 2

## GJM1555C1H6R0CB01D
designator C?  Capacitance: 6pF  (hidden comment: *)
Capacitor, Ceramic (MLCC), 6pF, ±0.25pF, 50V, C0G, ±0.25pF, SMD 0402; Manufacturer: Murata Electronics; Manufacturer Part Number: GJM1555C1H6R0CB01D
footprint CAP-0402 (0402 (1005M) Capacitor)
pins: 1, 2

## GJM1555C1H6R2BB01D
designator C?  Capacitance: 6.2pF  (hidden comment: *)
Capacitor, Ceramic (MLCC), 6.2pF, ±0.1pF, 50V, C0G, ±0.1pF, SMD 0402; Manufacturer: Murata Electronics; Manufacturer Part Number: GJM1555C1H6R2BB01D
footprint CAP-0402 (0402 (1005M) Capacitor)
pins: 1, 2

## GJM1555C1H6R2CB01D
designator C?  Capacitance: 6.2pF  (hidden comment: *)
Capacitor, Ceramic (MLCC), 6.2pF, ±0.25pF, 50V, C0G, ±0.25pF, SMD 0402; Manufacturer: Murata Electronics; Manufacturer Part Number: GJM1555C1H6R2CB01D
footprint CAP-0402 (0402 (1005M) Capacitor)
pins: 1, 2

## GJM1555C1H6R2DB01D
designator C?  Capacitance: 6.2pF  (hidden comment: *)
Capacitor, Ceramic (MLCC), 6.2pF, ±0.5pF, 50V, C0G, ±0.5pF, SMD 0402; Manufacturer: Murata Electronics; Manufacturer Part Number: GJM1555C1H6R2DB01D
footprint CAP-0402 (0402 (1005M) Capacitor)
pins: 1, 2

## GJM1555C1H6R8BB01D
designator C?  Capacitance: 6.8pF  (hidden comment: *)
Capacitor, Ceramic (MLCC), 6.8pF, ±0.1pF, 50V, C0G, ±0.1pF, SMD 0402; Manufacturer: Murata Electronics; Manufacturer Part Number: GJM1555C1H6R8BB01D
footprint CAP-0402 (0402 (1005M) Capacitor)
pins: 1, 2

## GJM1555C1H6R8CB01D
designator C?  Capacitance: 6.8pF  (hidden comment: *)
Capacitor, Ceramic (MLCC), 6.8pF, ±0.25pF, 50V, C0G, ±0.25pF, SMD 0402; Manufacturer: Murata Electronics; Manufacturer Part Number: GJM1555C1H6R8CB01D
footprint CAP-0402 (0402 (1005M) Capacitor)
pins: 1, 2

## GJM1555C1H7R0BB01D
designator C?  Capacitance: 7pF  (hidden comment: *)
Capacitor, Ceramic (MLCC), 7pF, ±0.1pF, 50V, C0G, ±0.1pF, SMD 0402; Manufacturer: Murata Electronics; Manufacturer Part Number: GJM1555C1H7R0BB01D
footprint CAP-0402 (0402 (1005M) Capacitor)
pins: 1, 2

## GJM1555C1H7R5WB01D
designator C?  Capacitance: 7.5pF  (hidden comment: *)
Capacitor, Ceramic (MLCC), 7.5pF, ±0.05pF, 50V, C0G, ±0.05pF, SMD 0402; Manufacturer: Murata Electronics; Manufacturer Part Number: GJM1555C1H7R5WB01D
footprint CAP-0402 (0402 (1005M) Capacitor)
pins: 1, 2

## GJM1555C1H8R0BB01D
designator C?  Capacitance: 8pF  (hidden comment: *)
Capacitor, Ceramic (MLCC), 8pF, ±0.1pF, 50V, C0G, ±0.1pF, SMD 0402; Manufacturer: Murata Electronics; Manufacturer Part Number: GJM1555C1H8R0BB01D
footprint CAP-0402 (0402 (1005M) Capacitor)
pins: 1, 2

## GJM1555C1H8R2BB01D
designator C?  Capacitance: 8.2pF  (hidden comment: *)
Capacitor, Ceramic (MLCC), 8.2pF, ±0.1pF, 50V, C0G, ±0.1pF, SMD 0402; Manufacturer: Murata Electronics; Manufacturer Part Number: GJM1555C1H8R2BB01D
footprint CAP-0402 (0402 (1005M) Capacitor)
pins: 1, 2

## GJM1555C1H8R2CB01D
designator C?  Capacitance: 8.2pF  (hidden comment: *)
Capacitor, Ceramic (MLCC), 8.2pF, ±0.25pF, 50V, C0G, ±0.25pF, SMD 0402; Manufacturer: Murata Electronics; Manufacturer Part Number: GJM1555C1H8R2CB01D
footprint CAP-0402 (0402 (1005M) Capacitor)
pins: 1, 2

## GJM1555C1H8R7BB01D
designator C?  Capacitance: 8.7pF  (hidden comment: *)
Capacitor, Ceramic (MLCC), 8.7pF, ±0.1pF, 50V, C0G, ±0.1pF, SMD 0402; Manufacturer: Murata Electronics; Manufacturer Part Number: GJM1555C1H8R7BB01D
footprint CAP-0402 (0402 (1005M) Capacitor)
pins: 1, 2

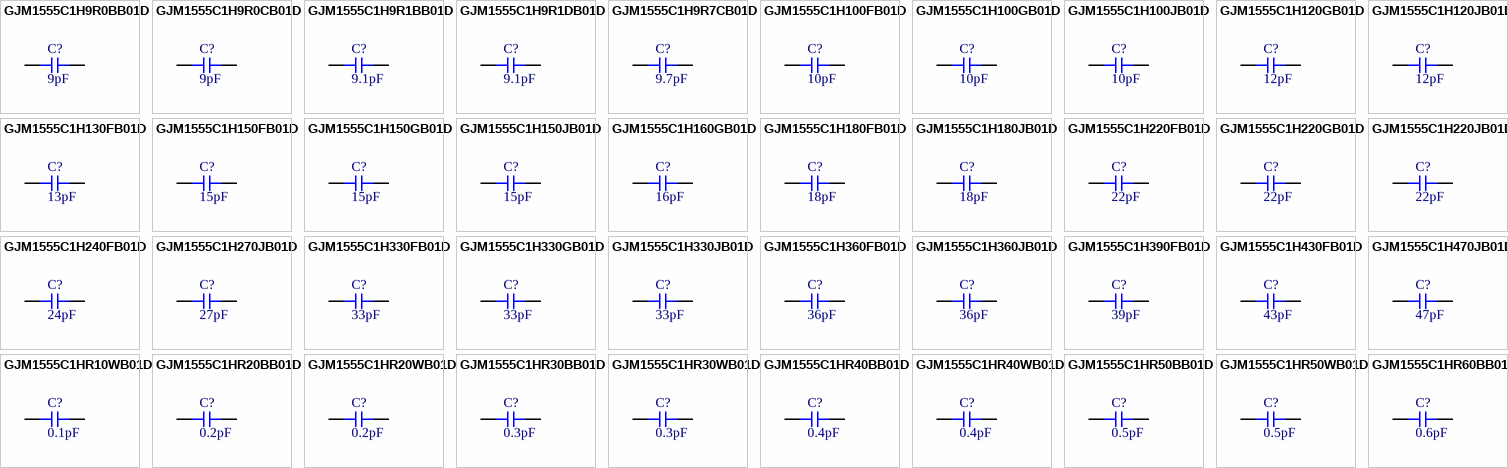
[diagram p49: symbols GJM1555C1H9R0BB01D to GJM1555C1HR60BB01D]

## GJM1555C1H9R0BB01D
designator C?  Capacitance: 9pF  (hidden comment: *)
Capacitor, Ceramic (MLCC), 9pF, ±0.1pF, 50V, C0G, ±0.1pF, SMD 0402; Manufacturer: Murata Electronics; Manufacturer Part Number: GJM1555C1H9R0BB01D
footprint CAP-0402 (0402 (1005M) Capacitor)
pins: 1, 2

## GJM1555C1H9R0CB01D
designator C?  Capacitance: 9pF  (hidden comment: *)
Capacitor, Ceramic (MLCC), 9pF, ±0.25pF, 50V, C0G, ±0.25pF, SMD 0402; Manufacturer: Murata Electronics; Manufacturer Part Number: GJM1555C1H9R0CB01D
footprint CAP-0402 (0402 (1005M) Capacitor)
pins: 1, 2

## GJM1555C1H9R1BB01D
designator C?  Capacitance: 9.1pF  (hidden comment: *)
Capacitor, Ceramic (MLCC), 9.1pF, ±0.1pF, 50V, C0G, ±0.1pF, SMD 0402; Manufacturer: Murata Electronics; Manufacturer Part Number: GJM1555C1H9R1BB01D
footprint CAP-0402 (0402 (1005M) Capacitor)
pins: 1, 2

## GJM1555C1H9R1DB01D
designator C?  Capacitance: 9.1pF  (hidden comment: *)
Capacitor, Ceramic (MLCC), 9.1pF, ±0.5pF, 50V, C0G, ±0.5pF, SMD 0402; Manufacturer: Murata Electronics; Manufacturer Part Number: GJM1555C1H9R1DB01D
footprint CAP-0402 (0402 (1005M) Capacitor)
pins: 1, 2

## GJM1555C1H9R7CB01D
designator C?  Capacitance: 9.7pF  (hidden comment: *)
Capacitor, Ceramic (MLCC), 9.7pF, ±0.25pF, 50V, C0G, ±0.25pF, SMD 0402; Manufacturer: Murata Electronics; Manufacturer Part Number: GJM1555C1H9R7CB01D
footprint CAP-0402 (0402 (1005M) Capacitor)
pins: 1, 2

## GJM1555C1H100FB01D
designator C?  Capacitance: 10pF  (hidden comment: *)
Capacitor, Ceramic (MLCC), 10pF, ±1%, ±1%, SMD 0402; Manufacturer: Murata Electronics; Manufacturer Part Number: GJM1555C1H100FB01D
footprint CAP-0402 (0402 (1005M) Capacitor)
pins: 1, 2

## GJM1555C1H100GB01D
designator C?  Capacitance: 10pF  (hidden comment: *)
Capacitor, Ceramic (MLCC), 10pF, ±2%, 50V, C0G, ±2%, SMD 0402; Manufacturer: Murata Electronics; Manufacturer Part Number: GJM1555C1H100GB01D
footprint CAP-0402 (0402 (1005M) Capacitor)
pins: 1, 2

## GJM1555C1H100JB01D
designator C?  Capacitance: 10pF  (hidden comment: *)
Capacitor, Ceramic (MLCC), 10pF, ±5%, 50V, C0G, ±5%, SMD 0402; Manufacturer: Murata Electronics; Manufacturer Part Number: GJM1555C1H100JB01D
footprint CAP-0402 (0402 (1005M) Capacitor)
pins: 1, 2

## GJM1555C1H120GB01D
designator C?  Capacitance: 12pF  (hidden comment: *)
Capacitor, Ceramic (MLCC), 12pF, ±2%, 50V, C0G, ±2%, SMD 0402; Manufacturer: Murata Electronics; Manufacturer Part Number: GJM1555C1H120GB01D
footprint CAP-0402 (0402 (1005M) Capacitor)
pins: 1, 2

## GJM1555C1H120JB01D
designator C?  Capacitance: 12pF  (hidden comment: *)
Capacitor, Ceramic (MLCC), 12pF, ±5%, 50V, C0G, ±5%, SMD 0402; Manufacturer: Murata Electronics; Manufacturer Part Number: GJM1555C1H120JB01D
footprint CAP-0402 (0402 (1005M) Capacitor)
pins: 1, 2

## GJM1555C1H130FB01D
designator C?  Capacitance: 13pF  (hidden comment: *)
Capacitor, Ceramic (MLCC), 13pF, ±1%, 50V, C0G, ±1%, SMD 0402; Manufacturer: Murata Electronics; Manufacturer Part Number: GJM1555C1H130FB01D
footprint CAP-0402 (0402 (1005M) Capacitor)
pins: 1, 2

## GJM1555C1H150FB01D
designator C?  Capacitance: 15pF  (hidden comment: *)
Capacitor, Ceramic (MLCC), 15pF, ±1%, 50V, C0G, ±1%, SMD 0402; Manufacturer: Murata Electronics; Manufacturer Part Number: GJM1555C1H150FB01D
footprint CAP-0402 (0402 (1005M) Capacitor)
pins: 1, 2

## GJM1555C1H150GB01D
designator C?  Capacitance: 15pF  (hidden comment: *)
Capacitor, Ceramic (MLCC), 15pF, ±2%, ±2%, SMD 0402; Manufacturer: Murata Electronics; Manufacturer Part Number: GJM1555C1H150GB01D
footprint CAP-0402 (0402 (1005M) Capacitor)
pins: 1, 2

## GJM1555C1H150JB01D
designator C?  Capacitance: 15pF  (hidden comment: *)
Capacitor, Ceramic (MLCC), 15pF, ±5%, 50V, C0G, ±5%, SMD 0402; Manufacturer: Murata Electronics; Manufacturer Part Number: GJM1555C1H150JB01D
footprint CAP-0402 (0402 (1005M) Capacitor)
pins: 1, 2

## GJM1555C1H160GB01D
designator C?  Capacitance: 16pF  (hidden comment: *)
Capacitor, Ceramic (MLCC), 16pF, ±2%, 50V, C0G, ±2%, SMD 0402; Manufacturer: Murata Electronics; Manufacturer Part Number: GJM1555C1H160GB01D
footprint CAP-0402 (0402 (1005M) Capacitor)
pins: 1, 2

## GJM1555C1H180FB01D
designator C?  Capacitance: 18pF  (hidden comment: *)
Capacitor, Ceramic (MLCC), 18pF, ±1%, 50V, C0G, ±1%, SMD 0402; Manufacturer: Murata Electronics; Manufacturer Part Number: GJM1555C1H180FB01D
footprint CAP-0402 (0402 (1005M) Capacitor)
pins: 1, 2

## GJM1555C1H180JB01D
designator C?  Capacitance: 18pF  (hidden comment: *)
Capacitor, Ceramic (MLCC), 18pF, ±5%, 50V, C0G, ±5%, SMD 0402; Manufacturer: Murata Electronics; Manufacturer Part Number: GJM1555C1H180JB01D
footprint CAP-0402 (0402 (1005M) Capacitor)
pins: 1, 2

## GJM1555C1H220FB01D
designator C?  Capacitance: 22pF  (hidden comment: *)
Capacitor, Ceramic (MLCC), 22pF, ±1%, ±1%, SMD 0402; Manufacturer: Murata Electronics; Manufacturer Part Number: GJM1555C1H220FB01D
footprint CAP-0402 (0402 (1005M) Capacitor)
pins: 1, 2

## GJM1555C1H220GB01D
designator C?  Capacitance: 22pF  (hidden comment: *)
Capacitor, Ceramic (MLCC), 22pF, ±2%, 50V, C0G, ±2%, SMD 0402; Manufacturer: Murata Electronics; Manufacturer Part Number: GJM1555C1H220GB01D
footprint CAP-0402 (0402 (1005M) Capacitor)
pins: 1, 2

## GJM1555C1H220JB01D
designator C?  Capacitance: 22pF  (hidden comment: *)
Capacitor, Ceramic (MLCC), 22pF, ±5%, 50V, C0G, ±5%, SMD 0402; Manufacturer: Murata Electronics; Manufacturer Part Number: GJM1555C1H220JB01D
footprint CAP-0402 (0402 (1005M) Capacitor)
pins: 1, 2

## GJM1555C1H240FB01D
designator C?  Capacitance: 24pF  (hidden comment: *)
Capacitor, Ceramic (MLCC), 24pF, ±1%, 50V, C0G, ±1%, SMD 0402; Manufacturer: Murata Electronics; Manufacturer Part Number: GJM1555C1H240FB01D
footprint CAP-0402 (0402 (1005M) Capacitor)
pins: 1, 2

## GJM1555C1H270JB01D
designator C?  Capacitance: 27pF  (hidden comment: *)
Capacitor, Ceramic (MLCC), 27pF, ±5%, 50V, C0G, ±5%, SMD 0402; Manufacturer: Murata Electronics; Manufacturer Part Number: GJM1555C1H270JB01D
footprint CAP-0402 (0402 (1005M) Capacitor)
pins: 1, 2

## GJM1555C1H330FB01D
designator C?  Capacitance: 33pF  (hidden comment: *)
Capacitor, Ceramic (MLCC), 33pF, ±1%, 50V, C0G, ±1%, SMD 0402; Manufacturer: Murata Electronics; Manufacturer Part Number: GJM1555C1H330FB01D
footprint CAP-0402 (0402 (1005M) Capacitor)
pins: 1, 2

## GJM1555C1H330GB01D
designator C?  Capacitance: 33pF  (hidden comment: *)
Capacitor, Ceramic (MLCC), 33pF, ±2%, 50V, C0G, ±2%, SMD 0402; Manufacturer: Murata Electronics; Manufacturer Part Number: GJM1555C1H330GB01D
footprint CAP-0402 (0402 (1005M) Capacitor)
pins: 1, 2

## GJM1555C1H330JB01D
designator C?  Capacitance: 33pF  (hidden comment: *)
Capacitor, Ceramic (MLCC), 33pF, ±5%, ±5%, SMD 0402; Manufacturer: Murata Electronics; Manufacturer Part Number: GJM1555C1H330JB01D
footprint CAP-0402 (0402 (1005M) Capacitor)
pins: 1, 2

## GJM1555C1H360FB01D
designator C?  Capacitance: 36pF  (hidden comment: *)
Capacitor, Ceramic (MLCC), 36pF, ±1%, 50V, C0G, ±1%, SMD 0402; Manufacturer: Murata Electronics; Manufacturer Part Number: GJM1555C1H360FB01D
footprint CAP-0402 (0402 (1005M) Capacitor)
pins: 1, 2

## GJM1555C1H360JB01D
designator C?  Capacitance: 36pF  (hidden comment: *)
Capacitor, Ceramic (MLCC), 36pF, ±5%, 50V, C0G, ±5%, SMD 0402; Manufacturer: Murata Electronics; Manufacturer Part Number: GJM1555C1H360JB01D
footprint CAP-0402 (0402 (1005M) Capacitor)
pins: 1, 2

## GJM1555C1H390FB01D
designator C?  Capacitance: 39pF  (hidden comment: *)
Capacitor, Ceramic (MLCC), 39pF, ±1%, ±1%, SMD 0402; Manufacturer: Murata Electronics; Manufacturer Part Number: GJM1555C1H390FB01D
footprint CAP-0402 (0402 (1005M) Capacitor)
pins: 1, 2

## GJM1555C1H430FB01D
designator C?  Capacitance: 43pF  (hidden comment: *)
Capacitor, Ceramic (MLCC), 43pF, ±1%, 50V, C0G, ±1%, SMD 0402; Manufacturer: Murata Electronics; Manufacturer Part Number: GJM1555C1H430FB01D
footprint CAP-0402 (0402 (1005M) Capacitor)
pins: 1, 2

## GJM1555C1H470JB01D
designator C?  Capacitance: 47pF  (hidden comment: *)
Capacitor, Ceramic (MLCC), 47pF, ±5%, 50V, C0G, ±5%, SMD 0402; Manufacturer: Murata Electronics; Manufacturer Part Number: GJM1555C1H470JB01D
footprint CAP-0402 (0402 (1005M) Capacitor)
pins: 1, 2

## GJM1555C1HR10WB01D
designator C?  Capacitance: 0.1pF  (hidden comment: *)
Capacitor, Ceramic (MLCC), 0.1pF, ±0.05pF, 50V, C0G, ±0.05pF, SMD 0402; Manufacturer: Murata Electronics; Manufacturer Part Number: GJM1555C1HR10WB01D
footprint CAP-0402 (0402 (1005M) Capacitor)
pins: 1, 2

## GJM1555C1HR20BB01D
designator C?  Capacitance: 0.2pF  (hidden comment: *)
Capacitor, Ceramic (MLCC), 0.2pF, ±0.1pF, 50V, C0G, ±0.1pF, SMD 0402; Manufacturer: Murata Electronics; Manufacturer Part Number: GJM1555C1HR20BB01D
footprint CAP-0402 (0402 (1005M) Capacitor)
pins: 1, 2

## GJM1555C1HR20WB01D
designator C?  Capacitance: 0.2pF  (hidden comment: *)
Capacitor, Ceramic (MLCC), 0.2pF, ±0.05pF, 50V, C0G, ±0.05pF, SMD 0402; Manufacturer: Murata Electronics; Manufacturer Part Number: GJM1555C1HR20WB01D
footprint CAP-0402 (0402 (1005M) Capacitor)
pins: 1, 2

## GJM1555C1HR30BB01D
designator C?  Capacitance: 0.3pF  (hidden comment: *)
Capacitor, Ceramic (MLCC), 0.3pF, ±0.1pF, 50V, C0G, ±0.1pF, SMD 0402; Manufacturer: Murata Electronics; Manufacturer Part Number: GJM1555C1HR30BB01D
footprint CAP-0402 (0402 (1005M) Capacitor)
pins: 1, 2

## GJM1555C1HR30WB01D
designator C?  Capacitance: 0.3pF  (hidden comment: *)
Capacitor, Ceramic (MLCC), 0.3pF, ±0.05pF, 50V, C0G, ±0.05pF, SMD 0402; Manufacturer: Murata Electronics; Manufacturer Part Number: GJM1555C1HR30WB01D
footprint CAP-0402 (0402 (1005M) Capacitor)
pins: 1, 2

## GJM1555C1HR40BB01D
designator C?  Capacitance: 0.4pF  (hidden comment: *)
Capacitor, Ceramic (MLCC), 0.4pF, ±0.1pF, 50V, C0G, ±0.1pF, SMD 0402; Manufacturer: Murata Electronics; Manufacturer Part Number: GJM1555C1HR40BB01D
footprint CAP-0402 (0402 (1005M) Capacitor)
pins: 1, 2

## GJM1555C1HR40WB01D
designator C?  Capacitance: 0.4pF  (hidden comment: *)
Capacitor, Ceramic (MLCC), 0.4pF, ±0.05pF, 50V, C0G, ±0.05pF, SMD 0402; Manufacturer: Murata Electronics; Manufacturer Part Number: GJM1555C1HR40WB01D
footprint CAP-0402 (0402 (1005M) Capacitor)
pins: 1, 2

## GJM1555C1HR50BB01D
designator C?  Capacitance: 0.5pF  (hidden comment: *)
Capacitor, Ceramic (MLCC), 0.5pF, ±0.1pF, 50V, C0G, ±0.1pF, SMD 0402; Manufacturer: Murata Electronics; Manufacturer Part Number: GJM1555C1HR50BB01D
footprint CAP-0402 (0402 (1005M) Capacitor)
pins: 1, 2

## GJM1555C1HR50WB01D
designator C?  Capacitance: 0.5pF  (hidden comment: *)
Capacitor, Ceramic (MLCC), 0.5pF, ±0.05pF, 50V, C0G, ±0.05pF, SMD 0402; Manufacturer: Murata Electronics; Manufacturer Part Number: GJM1555C1HR50WB01D
footprint CAP-0402 (0402 (1005M) Capacitor)
pins: 1, 2

## GJM1555C1HR60BB01D
designator C?  Capacitance: 0.6pF  (hidden comment: *)
Capacitor, Ceramic (MLCC), 0.6pF, ±0.1pF, 50V, C0G, ±0.1pF, SMD 0402; Manufacturer: Murata Electronics; Manufacturer Part Number: GJM1555C1HR60BB01D
footprint CAP-0402 (0402 (1005M) Capacitor)
pins: 1, 2

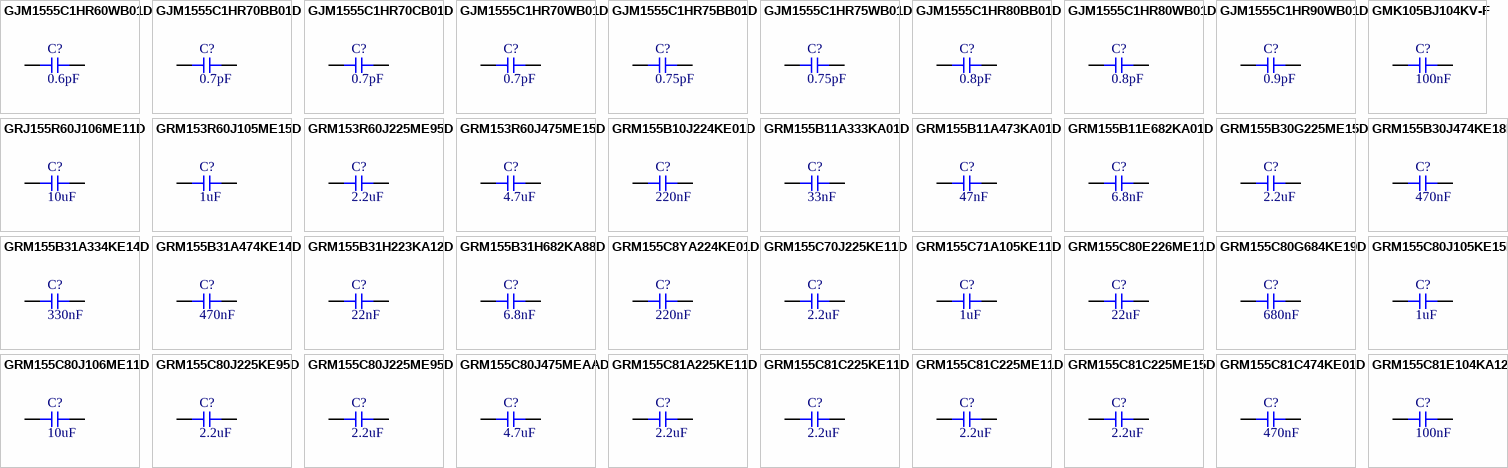
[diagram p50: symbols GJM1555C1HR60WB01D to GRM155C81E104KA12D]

## GJM1555C1HR60WB01D
designator C?  Capacitance: 0.6pF  (hidden comment: *)
Capacitor, Ceramic (MLCC), 0.6pF, ±0.05pF, 50V, C0G, ±0.05pF, SMD 0402; Manufacturer: Murata Electronics; Manufacturer Part Number: GJM1555C1HR60WB01D
footprint CAP-0402 (0402 (1005M) Capacitor)
pins: 1, 2

## GJM1555C1HR70BB01D
designator C?  Capacitance: 0.7pF  (hidden comment: *)
Capacitor, Ceramic (MLCC), 0.7pF, ±0.1pF, 50V, C0G, ±0.1pF, SMD 0402; Manufacturer: Murata Electronics; Manufacturer Part Number: GJM1555C1HR70BB01D
footprint CAP-0402 (0402 (1005M) Capacitor)
pins: 1, 2

## GJM1555C1HR70CB01D
designator C?  Capacitance: 0.7pF  (hidden comment: *)
Capacitor, Ceramic (MLCC), 0.7pF, ±0.25pF, 50V, C0G, ±0.25pF, SMD 0402; Manufacturer: Murata Electronics; Manufacturer Part Number: GJM1555C1HR70CB01D
footprint CAP-0402 (0402 (1005M) Capacitor)
pins: 1, 2

## GJM1555C1HR70WB01D
designator C?  Capacitance: 0.7pF  (hidden comment: *)
Capacitor, Ceramic (MLCC), 0.7pF, ±0.05pF, 50V, C0G, ±0.05pF, SMD 0402; Manufacturer: Murata Electronics; Manufacturer Part Number: GJM1555C1HR70WB01D
footprint CAP-0402 (0402 (1005M) Capacitor)
pins: 1, 2

## GJM1555C1HR75BB01D
designator C?  Capacitance: 0.75pF  (hidden comment: *)
Capacitor, Ceramic (MLCC), 0.75pF, ±0.1pF, 50V, C0G, ±0.1pF, SMD 0402; Manufacturer: Murata Electronics; Manufacturer Part Number: GJM1555C1HR75BB01D
footprint CAP-0402 (0402 (1005M) Capacitor)
pins: 1, 2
